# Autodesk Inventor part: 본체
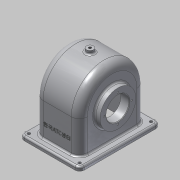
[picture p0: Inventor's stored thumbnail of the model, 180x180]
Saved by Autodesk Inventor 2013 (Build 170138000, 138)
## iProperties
Created: 2016-01
Part Number: 본체
Material: 알루미늄 6061
Document SubType Name: Modeling
Designer: Administrator
Density: 2.71 g/cm^3
Mass: 805.448 g
Surface Area: 985.542 cm^2
Volume: 297.213 cm^3
Author: Administrator
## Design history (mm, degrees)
sketch "스케치1"
  geometry: L1 (-57, 0)-(-57, -57); L2 (57, 0)-(57, -57); L3 (-57, -57)-(57, -57); A1 r 57 centre (0, 0) between (57, 0) and (-57, 0); 1 further point
  constraints: 6 end point, 2 point on circle, 2 tangent, 1 centre point, 1 coincident, 1 parallel, 1 perpendicular, 1 vertical
extrude "돌출1" new body sketch "스케치1" stored distance "d4" = 77; taper "d5" = 0 deg
sketch "스케치2"
  geometry: L1 (6, -6)-(71, -6) reference; L2 (71, -6)-(71, -108) reference; L3 (71, -108)-(6, -108) reference; L4 (6, -108)-(6, -6) reference; L5 (-13.5, 13)-(90.5, 13); L6 (90.5, 13)-(90.5, -127); L7 (90.5, -127)-(-13.5, -127); L8 (-13.5, -127)-(-13.5, 13); 3 further points
  constraints: 8 end point, 2 midpoint, 2 parallel, 1 horizontal, 1 horizontal alignment, 1 perpendicular, 1 vertical alignment
extrude "돌출2" join sketch "스케치2" distance "d10" = 7; taper "d11" = 0 deg
sketch "스케치3"
  geometry: 2 further points
hole "구멍1" sketch "스케치3" at (-82.5, 5) diameter "d14" = 5; stored, may be unused: countersink angle "d18" = 90 deg, drill point angle "d20" = 118 deg; dims "d15" = 6, "d16" = 4, "d17" = 2, "d19" = 8
sketch "스케치4"
  geometry: L1 (64, 70)-(64, -70) reference; C1 r 31 at (4, 0)
  constraints: 1 centre point
extrude "돌출3" join sketch "스케치4" distance "d23" = 10; taper "d24" = 0 deg
sketch "스케치7"
  geometry: L1 (-51, 0)-(-51, -97.929); L2 (-51, -97.929)-(51, -97.929); L3 (51, -97.929)-(51, 0); A1 r 51 centre (0, 0) between (51, 0) and (-51, 0); 1 further point
  constraints: 6 end point, 2 point on circle, 2 tangent, 1 centre point, 1 coincident, 1 perpendicular, 1 vertical
extrude "돌출5" cut sketch "스케치7" stored distance "d37" = 67; taper "d38" = 0 deg
node "작업 평면2"
sketch "스케치8"
  geometry: C1 r 6 at (38.5, -57); 1 further point
  constraints: 1 centre point, 1 coincident
  dimensions: "d40" = 12 diameter of C1
extrude "돌출6" join sketch "스케치8" stored distance "d41" = 67; taper "d42" = 0 deg
sketch "스케치9"
  geometry: C1 r 6 at (0, 0) reference; 1 further point
  constraints: 1 coincident
hole "구멍3" sketch "스케치9" at (0, 0) diameter "d43" = 4.459; stored, may be unused: countersink angle "d47" = 90 deg, drill point angle "d49" = 118 deg; dims "d44" = 18, "d45" = 4, "d46" = 2, "d48" = 20
sketch "스케치10"
  geometry: L1 (33.5, 0)-(33.5, 51) reference; L2 (33.5, 0)-(33.5, -64) reference; L3 (33.5, -4)-(17.5, -4); L4 (-33.5, -64)-(33.5, -64) reference; L5 (17.5, -4)-(17.5, 24); L6 (17.5, 24)-(33.5, 37.426); 1 further point
  constraints: 6 end point, 2 perpendicular, 2 point on line
revolve "회전1" sketch "스케치10" stored, may be unused: angle "d53" = 90 deg
sketch "스케치11"
  geometry: L1 (38.5, 0)-(38.5, 57) reference; L2 (38.5, 0)-(38.5, -57) reference; L3 (36.929, -4)-(35.5, -4); L4 (-33.5, -64)-(33.5, -64) reference; L5 (36.929, -4)-(38.5, -4); L6 (35.5, 32.577)-(35.5, -4); L7 (17.5, 24)-(33.5, 37.426) reference; L8 (35.5, 32.577)-(38.5, 35.094); L9 (38.5, 35.094)-(38.5, -4); 1 further point
  constraints: 10 end point, 3 perpendicular, 2 point on line, 1 collinear, 1 parallel
revolve "회전2" sketch "스케치11" stored, may be unused: angle "d59" = 90 deg
sketch "스케치12"
  geometry: C1 r 31 at (0, 0) reference; 2 further points
  constraints: 1 coincident
hole "구멍4" sketch "스케치12" at (0, 0) diameter "d60" = 40; stored, may be unused: countersink angle "d64" = 90 deg, drill point angle "d66" = 0 deg; dims "d61" = 18, "d62" = 4, "d63" = 2, "d65" = 20
sketch "스케치14"
  geometry: 2 further points
hole "구멍5" sketch "스케치14" at (28, 0) diameter "d74" = 2.459; stored, may be unused: countersink angle "d78" = 90 deg, drill point angle "d80" = 118 deg; dims "d75" = 7, "d76" = 4, "d77" = 2, "d79" = 9
sketch "스케치15"
  geometry: 2 further points
hole "구멍6" sketch "스케치15" at (-24, 0) diameter "d85" = 2.459; stored, may be unused: countersink angle "d89" = 90 deg, drill point angle "d91" = 118 deg; dims "d86" = 6, "d87" = 4, "d88" = 2, "d90" = 8
sketch "스케치16"
  geometry: L1 (77, 0)-(0, 0) reference; L2 (90.5, -64)-(-13.5, -64) reference; 3 further points
  constraints: 1 midpoint, 1 vertical alignment, 1 other
feature "엠보싱1" sketch "스케치16" dims "d96" = 0.5, "d97" = 0
chamfer "모따기1" distance "d98" = 1; stored, may be unused: second distance "d99" = 2, angle "d100" = 45 deg
fillet "모깎기2" dims "d101" = 14, "d103" = 8, "d104" = 9, "d105" = 3
node "솔리드1"
mirror "대칭1"
mirror "대칭2"
pattern_circular "원형 패턴1" dims angle "d82" = 360 deg
pattern_circular "원형 패턴2" dims angle "d93" = 360 deg
other parameters: "d39" = -127
